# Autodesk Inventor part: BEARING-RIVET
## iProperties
Created: 2007-10
Part Number: BEARING-RIVET
Document SubType Name: Modeling
Material: Delrin, Black
Density: 1.425 g/cm^3
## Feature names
1. Base1
